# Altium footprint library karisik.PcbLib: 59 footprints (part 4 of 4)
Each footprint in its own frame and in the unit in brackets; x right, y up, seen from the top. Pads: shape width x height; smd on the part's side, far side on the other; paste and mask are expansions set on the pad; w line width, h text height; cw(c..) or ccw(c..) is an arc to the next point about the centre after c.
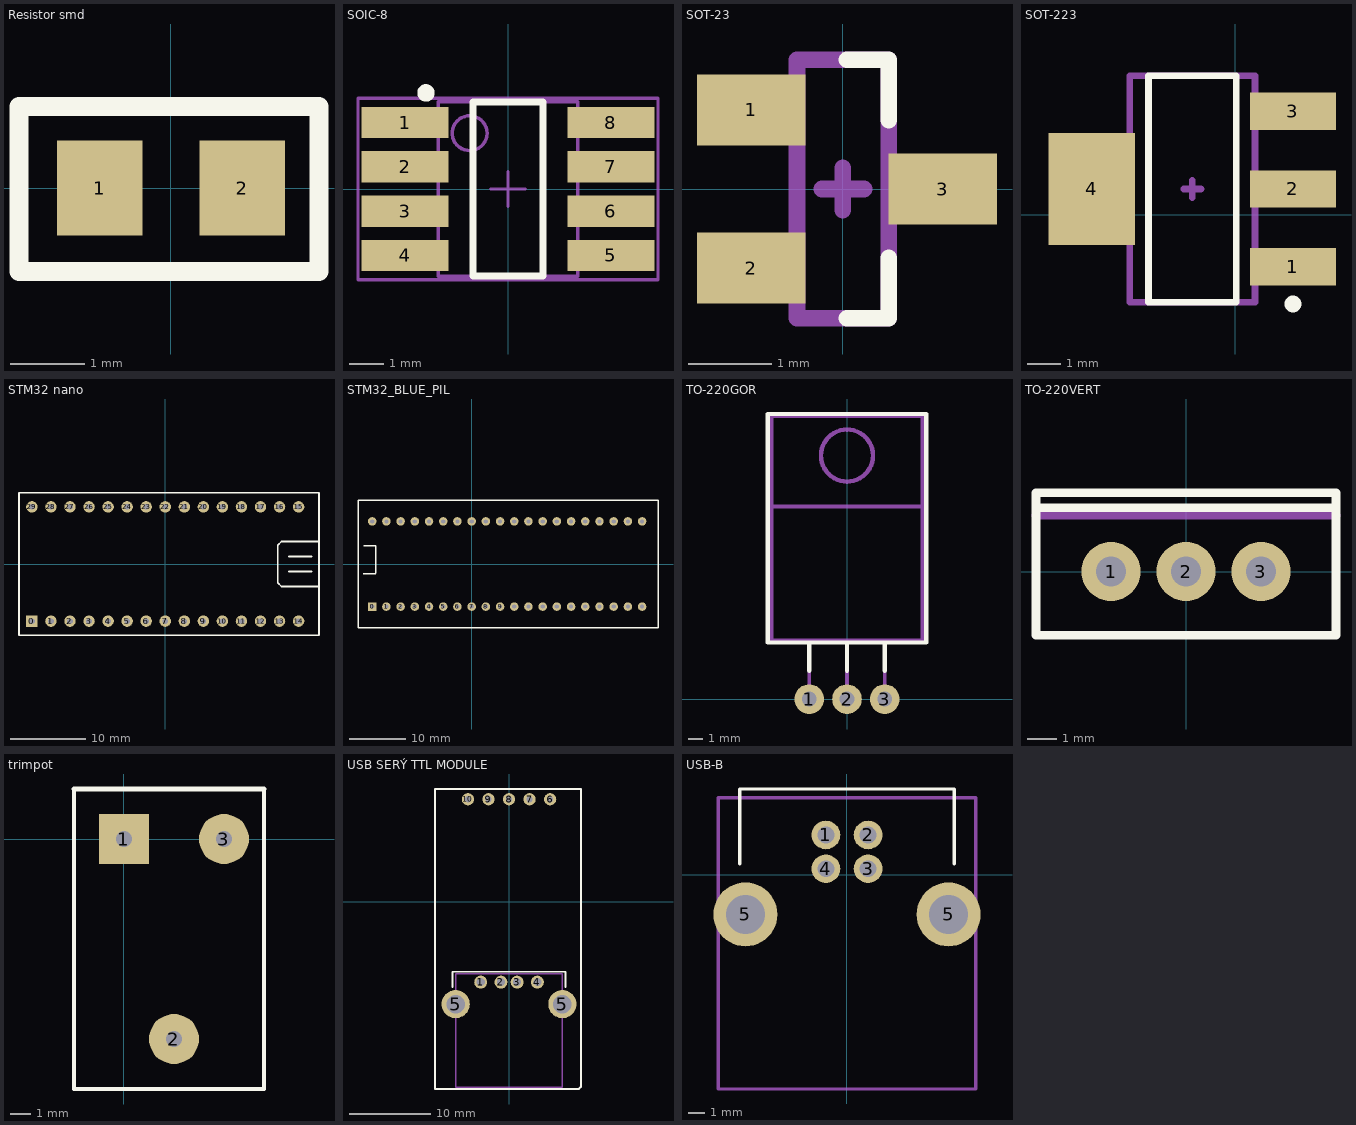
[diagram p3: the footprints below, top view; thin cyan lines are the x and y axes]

## Resistor smd [mil]
pads (2):
  rect 45x50 smd: 1(-37.5,0) 2(37.5,0)
Top Overlay:
  lines w10: -80,-44 78,-44 78,43 -80,43 -80,0 -80,-44

## SOIC-8 [mm]
height 1.75
pads (8):
  rect 2.5x0.9 smd: 1(-2.95,1.905) 2(-2.95,0.635) 3(-2.95,-0.635) 4(-2.95,-1.905) 5(2.95,-1.905) 6(2.95,-0.635) 7(2.95,0.635) 8(2.95,1.905)
Top Overlay:
  circle w0.25: c-2.35,2.755 r0.125
  lines w0.2: -1,-2.5 1,-2.5 1,2.5 -1,2.5 -1,-2.5
Mechanical 13:
  circle w0.1: c-1.1,1.6 r0.5
  lines w0.1: -2,-2.5 2,-2.5 2,2.5 -2,2.5 -2,-2.5
Mechanical 15:
  lines w0.1: -0.5,0 0.5,0 ; 0,-0.5 0,0.5 ; -4.3,-2.6 4.3,-2.6 4.3,2.6 -4.3,2.6 -4.3,-2.6
3D body: height 1.75, standoff 0, extent -3,-2.45 3,2.45

## SOT-23 [mm] "SOT23, 3-Leads, Body 3,1x2,5mm (max), Pitch 0,95mm, IPC Medium Density"
height 1.1
pads (3):
  rect 1.3x0.85 smd: 1(-1.1,0.95) 2(-1.1,-0.95) 3(1.2,0)
Top Overlay:
  lines w0.2: 0.05,-1.55 0.55,-1.55 0.55,-0.825 ; 0.05,1.55 0.55,1.55 0.55,0.825
Mechanical 13:
  lines w0.2: -0.55,-1.55 -0.55,1.55 0.55,1.55 0.55,-1.55 -0.55,-1.55
Mechanical 15:
  lines w0.2: -0.254,0 0.254,0 ; 0,-0.254 0,0.254
3D body: height 1, standoff -0.02, extent -1.27,-1.46 1.206,1.46

## SOT-223 [mm] "SOT223, 4-Leads, Body 6,7x7,3mm (max), Pitch 2,30mm, IPC Medium Density"
height 1.8
pads (4):
  rect 2.55x1.1 smd: 1(1.705,-1.538) 2(1.705,0.762) 3(1.705,3.062)
  rect 2.55x3.3 smd: 4(-4.245,0.762)
Top Overlay:
  circle w0.25: c1.705,-2.638 r0.125
  lines w0.2: -2.57,-2.588 -2.57,4.112 0.03,4.112 0.03,-2.588 -2.57,-2.588
Mechanical 13:
  lines w0.2: -3.12,-2.588 -3.12,4.112 0.58,4.112 0.58,-2.588 -3.12,-2.588
  text ".Designator" at -0.889,2.032 h2.5
Mechanical 15:
  lines w0.2: -1.524,0.762 -1.016,0.762 ; -1.27,0.508 -1.27,1.016
3D body: height 1.6, standoff -0.05, extent -4.826,-2.488 2.174,4.012

## STM32 nano [mil] "arduino nano STM32"
height 1700
pads (30):
  rect 60x60 hole 30: 0(-700,-300)
  round 60 hole 30: 1(-600,-300) 2(-500,-300) 3(-400,-300) 4(-300,-300) 5(-200,-300) 6(-100,-300) 7(0,-300) 8(100,-300) 9(200,-300) 10(300,-300) 11(400,-300) 12(500,-300) 13(600,-300) 14(700,-300) 15(700,300) 16(600,300) 17(500,300) 18(400,300) 19(300,300) 20(200,300) 21(100,300) 22(0,300) 23(-100,300) 24(-200,300) 25(-300,300) 26(-400,300) 27(-500,300) 28(-600,300) 29(-700,300)
Top Overlay:
  lines w10: 649.61,-39.37 767.72,-39.37 ; 649.61,39.37 767.72,39.37 ; 807.09,-118.11 629.92,-118.11 610.24,-118.11 590.55,-98.43 590.55,-59.06 590.55,98.43 610.24,118.11 807.09,118.11 ; -767.72,-374.02 -767.72,314.96 -767.72,374.02 807.09,374.02 807.09,334.65 807.09,-374.02 -767.72,-374.02

## STM32_BLUE_PIL [mil] "arduino nano"
height 1700
pads (40):
  rect 60x60 hole 30: 0(-700,-300)
  round 60 hole 30: 1(-600,-300) 2(-500,-300) 3(-400,-300) 4(-300,-300) 5(-200,-300) 6(-100,-300) 7(0,-300) 8(100,-300) 9(200,-300) 10(300,-300) 11(400,-300) 12(500,-300) 13(600,-300) 14(700,-300) 15(800,-300) 16(900,-300) 17(1000,-300) 18(1100,-300) 19(1200,-300) 20(1200,300) 21(1100,300) 22(1000,300) 23(900,300) 24(800,300) 25(700,300) 26(600,300) 27(500,300) 28(400,300) 29(300,300) 30(200,300) 31(100,300) 32(0,300) 33(-100,300) 34(-200,300) 35(-300,300) 36(-400,300) 37(-500,300) 38(-600,300) 39(-700,300)
Top Overlay:
  lines w10: -761.72,-70 -675,-70 ; -759,127 -676,127 -676,-65 ; -800,-450 -800,282.68 -800,450 1312,450 1312,-450 -800,-450

## TO-220GOR [mm]
height 1.8
pads (3):
  round 2 hole 1: 1(-2.54,0) 2(0,0) 3(2.54,0)
Top Overlay:
  lines w0.3: -2.54,1.905 -2.54,3.81 ; 0,1.905 0,3.81 ; 2.54,1.905 2.54,3.81 ; -5.334,3.81 5.334,3.81 5.334,19.177 -5.334,19.177 -5.334,3.81
Mechanical 13:
  circle w0.3: c0,16.383 r1.75
  lines w0.254: -5.08,12.954 5.08,12.954 ; -2.54,0 -2.54,3.937 0,3.937 0,0 ; 2.54,0 2.54,3.937 ; -5.08,3.937 5.08,3.937 5.08,19.05 -5.08,19.05 -5.08,3.937
  text ".Designator" at -2.921,6.604 h1.5
3D body: height 4.2, standoff -3, extent -5.08,-0.381 5.08,19.109

## TO-220VERT [mm]
height 1.8
pads (3):
  round 2 hole 1: 1(-2.54,0) 2(0,0) 3(2.54,0)
Top Overlay:
  lines w0.3: -5.08,2.159 5.08,2.159 ; -5.08,-2.159 5.08,-2.159 5.08,2.667 -5.08,2.667 -5.08,-2.159
Mechanical 13:
  lines w0.254: -5.08,-2.159 5.08,-2.159 5.08,2.667 -5.08,2.667 -5.08,-2.159
  lines w0.3: -5.08,1.905 5.08,1.905
  text ".Designator" at -3.302,-3.683 h1.5
3D body: height 20.86, standoff -3, extent -5.335,-2.159 5.335,2.671

## trimpot [mm]
pads (3):
  rect 2.5x2.5 hole 0.8: 1(0,0)
  round 2.5 hole 0.8: 2(2.5,-10) 3(5,0)
Top Overlay:
  lines w0.2: -2.5,2.5 -2.5,-12.5 7,-12.5 7,2.5
  lines w0.254: -2.5,2.5 7,2.5

## USB SERÝ TTL MODULE [mm]
height 5.08
pads (11):
  round 1.6 hole 1 paste-3: 1(-3.5,-9.948) 2(-1,-9.948) 3(1,-9.948) 4(3.5,-9.948)
  round 3.5 hole 2.3: 5(-6.6,-12.658) 5(6.6,-12.658)
  round 1.524 hole 0.762: 6(5.08,12.658) 7(2.54,12.658) 8(0,12.658) 9(-2.54,12.658) 10(-5.08,12.658)
Top Overlay:
  lines w0.2: -6.985,-10.583 -6.985,-8.678 6.985,-8.678 6.985,-10.583
  lines w0.254: -9.144,-23.156 8.636,-23.156 8.89,-22.902 8.89,13.928 -9.144,13.928 -9.144,-23.156
Mechanical 13:
  lines w0.2: -6.6,-22.948 -6.6,-8.932 6.6,-8.932 6.6,-22.948 0,-22.948 -6.6,-22.948
  text ".Designator" at -2.921,-12.488 h1.5
3D body: height 7.45, standoff -3.47, extent -7.9,-23.032 7.9,-8.932

## USB-B [mm]
pads (6):
  round 1.7 hole 1: 1(-1.25,2.355) 2(1.25,2.355) 3(1.25,0.355) 4(-1.25,0.355)
  round 3.8 hole 2.3: 5(-6.02,-2.355) 5(6.02,-2.355)
Top Overlay:
  lines w0.2: -6.35,0.635 -6.35,5.08 0,5.08 6.35,5.08 6.35,0.635
Mechanical 13:
  lines w0.2: -7.62,-12.7 -7.62,4.572 7.62,4.572 7.62,-12.7 -7.62,-12.7
  text ".Designator" at -3.111,-4.572 h2.5
3D body: height 11, standoff -4.42, extent -7.442,-12.555 7.442,4.445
